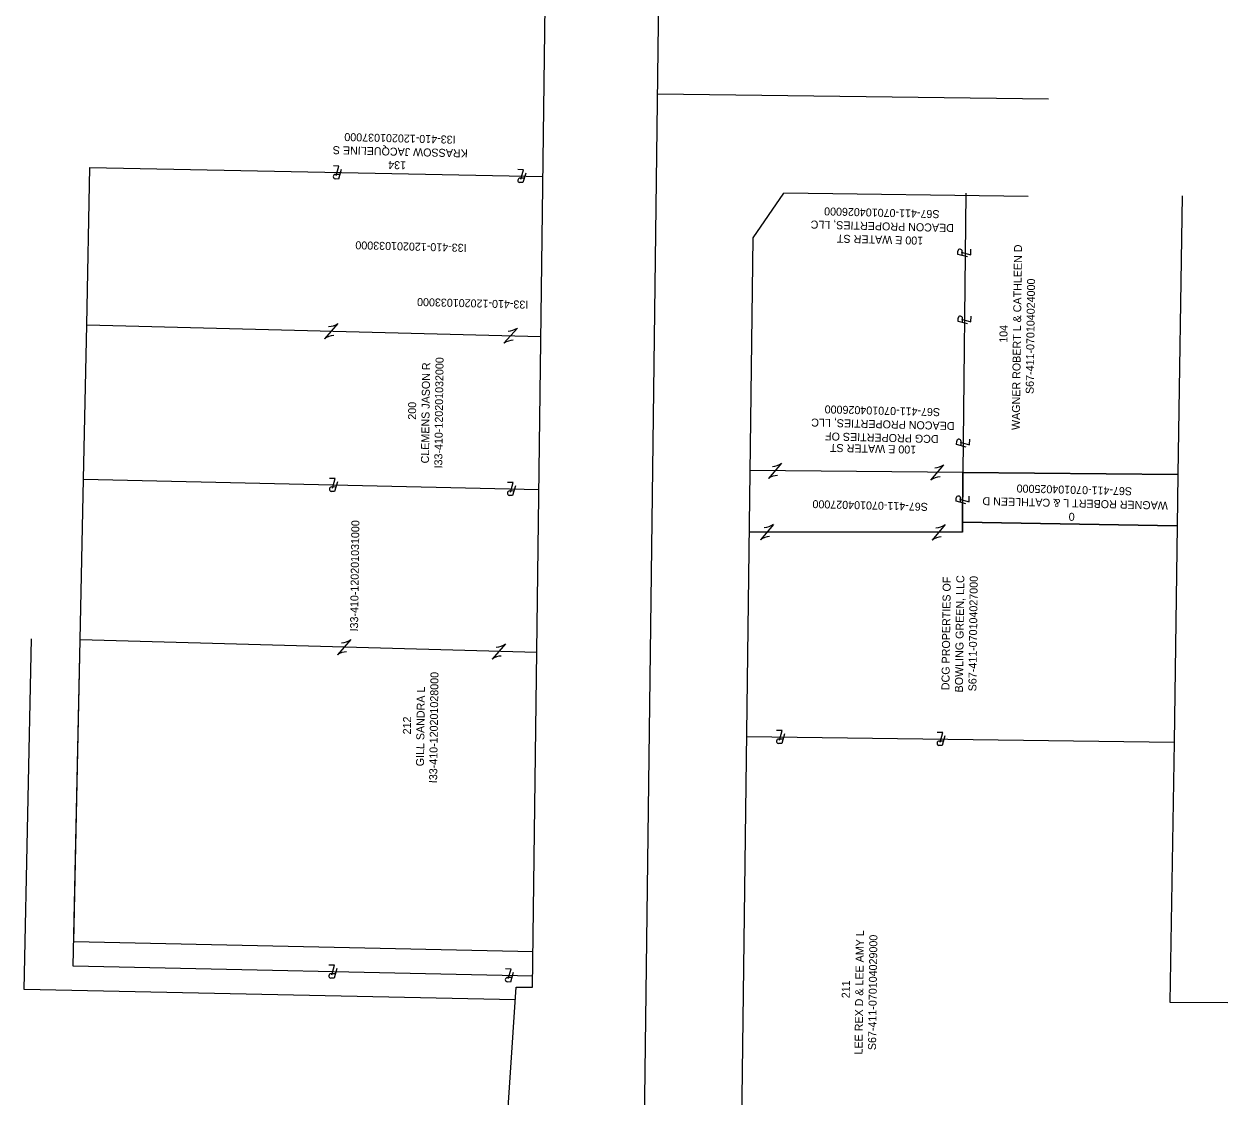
# Model space of a CAD drawing. Extents: x 1652206 to 1653153, y 604222 to 614600.
# Drawn here: x 1652350.6 to 1652721.5, y 606167.5 to 606498.1 of the extents above; entities that cross this region are included whole.
import ezdxf

# ---------------------------------------------------------------- set-up
doc = ezdxf.new("R2010")
doc.units = 0
for name, color, linetype in [('_CIVIL_CONSTRUCTION', 7, 'Continuous'), ('DT_X_Contour_Major', 7, 'Continuous'), ('GE_P_Alignment_100_Bearings', 7, 'Continuous'), ('GE_P_Alignment_100_Cardinal_Points', 7, 'Continuous'), ('GE_P_Alignment_100_Distances', 7, 'Continuous')]:
    doc.layers.add(name, color=color, linetype=linetype)

msp = doc.modelspace()

# ---------------------------------------------------------------- linework, layer by layer
at = {"layer": '_CIVIL_CONSTRUCTION'}
for p, q in [((1652516.96, 604222.43), (1652550.86, 606872.07)), ((1652666.28, 606474.95), (1652545.8, 606476.49))]:
    msp.add_line(p, q, dxfattribs=at)
at = {"layer": 'DT_X_Contour_Major'}
for p, q in [((1652350.6, 606200.67), (1652352.9, 606308.67)), ((1652365.91, 606215.35), (1652367.9, 606308.35)), ((1652507.48, 606212.3), (1652365.91, 606215.35)), ((1652502.01, 606197.42), (1652350.6, 606200.67))]:
    msp.add_line(p, q, dxfattribs=at)
at = {"layer": 'GE_P_Alignment_100_Bearings'}
for p, q in [((1652369.9, 606405.41), (1652370.9, 606453.91)), ((1652370.9, 606453.91), (1652510.47, 606451.15)), ((1652447.86, 606451.76), (1652446.56, 606451.79)), ((1652447.07, 606452.4), (1652447.07, 606452.4)), ((1652504.71, 606450.64), (1652503.41, 606450.66)), ((1652503.92, 606451.27), (1652503.92, 606451.27)), ((1652640.8, 606446.07), (1652639.83, 606359.91)), ((1652707.44, 606445.22), (1652706.07, 606359.35)), ((1652639.65, 606426.79), (1652639.66, 606428.09)), ((1652640.28, 606427.59), (1652640.28, 606427.59)), ((1652639.73, 606406.16), (1652639.75, 606407.45)), ((1652368.9, 606357.85), (1652369.9, 606405.41)), ((1652369.9, 606405.41), (1652509.84, 606401.9)), ((1652447.29, 606405.87), (1652443.17, 606401.17)), ((1652502.59, 606404.48), (1652498.47, 606399.79)), ((1652640.36, 606406.95), (1652640.36, 606406.95)), ((1652445.23, 606403.52), (1652445.23, 606403.52)), ((1652500.53, 606402.13), (1652500.53, 606402.13)), ((1652639.31, 606368.23), (1652639.32, 606369.52)), ((1652639.94, 606369.02), (1652639.94, 606369.02)), ((1652583.98, 606362.83), (1652579.94, 606358.06)), ((1652639.83, 606359.91), (1652574.32, 606360.52)), ((1652581.96, 606360.45), (1652581.96, 606360.45)), ((1652629.99, 606357.6), (1652634.04, 606362.36)), ((1652632.01, 606359.98), (1652632.01, 606359.98)), ((1652639.73, 606344.67), (1652639.83, 606359.91)), ((1652639.83, 606359.91), (1652639.73, 606344.67)), ((1652639.83, 606359.91), (1652706.07, 606359.35)), ((1652706.07, 606359.35), (1652639.83, 606359.91)), ((1652706.07, 606359.35), (1652705.85, 606343.47)), ((1652367.9, 606308.35), (1652368.9, 606357.85)), ((1652368.9, 606357.85), (1652509.24, 606354.7)), ((1652446.67, 606355.48), (1652445.37, 606355.51)), ((1652445.88, 606356.12), (1652445.88, 606356.12)), ((1652501.51, 606354.25), (1652500.22, 606354.28)), ((1652500.72, 606354.89), (1652500.72, 606354.89)), ((1652639.15, 606350.7), (1652639.16, 606352)), ((1652639.78, 606351.5), (1652639.78, 606351.5)), ((1652639.73, 606341.55), (1652639.73, 606344.67)), ((1652639.73, 606344.67), (1652705.85, 606343.47)), ((1652705.85, 606343.47), (1652639.73, 606344.67)), ((1652639.73, 606344.67), (1652639.73, 606341.55)), ((1652639.73, 606341.55), (1652574.07, 606341.59)), ((1652581.48, 606343.98), (1652577.47, 606339.19)), ((1652579.47, 606341.59), (1652579.47, 606341.59)), ((1652634.38, 606343.95), (1652630.37, 606339.15)), ((1652632.38, 606341.55), (1652632.38, 606341.55)), ((1652705.85, 606343.47), (1652704.91, 606276.91)), ((1652365.76, 606207.85), (1652367.9, 606308.35)), ((1652508.59, 606304.47), (1652367.9, 606308.35)), ((1652451.27, 606308.45), (1652447.14, 606303.76)), ((1652498.93, 606307.14), (1652494.8, 606302.45)), ((1652449.21, 606306.11), (1652449.21, 606306.11)), ((1652496.86, 606304.8), (1652496.86, 606304.8)), ((1652573.27, 606278.57), (1652704.91, 606276.91)), ((1652584.41, 606277.8), (1652583.12, 606277.82)), ((1652583.62, 606278.44), (1652583.62, 606278.44)), ((1652633.09, 606277.81), (1652633.09, 606277.81)), ((1652633.88, 606277.18), (1652632.59, 606277.2)), ((1652704.91, 606276.91), (1652703.61, 606196.79)), ((1652507.32, 606204.8), (1652365.76, 606207.85)), ((1652446.51, 606205.49), (1652445.21, 606205.52)), ((1652445.72, 606206.13), (1652445.72, 606206.13)), ((1652500.86, 606204.32), (1652499.56, 606204.35)), ((1652500.07, 606204.96), (1652500.07, 606204.96)), ((1652703.61, 606196.79), (1652721.52, 606196.61))]:
    msp.add_line(p, q, dxfattribs=at)
for points in [[(1652446.78, 606451.45), (1652447.63, 606454.39), (1652445.89, 606454.42)], [(1652448.31, 606453.34), (1652447.47, 606450.39), (1652446.44, 606450.42)], [(1652503.63, 606450.32), (1652504.48, 606453.26), (1652502.74, 606453.3)], [(1652505.16, 606452.22), (1652504.32, 606449.27), (1652503.29, 606449.29)], [(1652641.24, 606426.36), (1652638.28, 606427.16), (1652638.29, 606428.2)], [(1652639.32, 606427.86), (1652642.27, 606427.05), (1652642.28, 606428.8)], [(1652641.32, 606405.72), (1652638.36, 606406.53), (1652638.38, 606407.57)], [(1652639.41, 606407.23), (1652642.35, 606406.4), (1652642.37, 606408.15)], [(1652638.98, 606369.3), (1652641.93, 606368.47), (1652641.95, 606370.22)], [(1652640.89, 606367.79), (1652637.94, 606368.6), (1652637.95, 606369.64)], [(1652445.6, 606355.17), (1652446.45, 606358.1), (1652444.71, 606358.14)], [(1652447.13, 606357.06), (1652446.28, 606354.11), (1652445.25, 606354.14)], [(1652500.44, 606353.93), (1652501.29, 606356.87), (1652499.55, 606356.91)], [(1652501.97, 606355.83), (1652501.12, 606352.88), (1652500.09, 606352.91)], [(1652640.74, 606350.27), (1652637.78, 606351.07), (1652637.79, 606352.11)], [(1652638.82, 606351.77), (1652641.77, 606350.96), (1652641.78, 606352.71)], [(1652583.34, 606277.48), (1652584.17, 606280.43), (1652582.42, 606280.45)], [(1652584.85, 606279.39), (1652584.03, 606276.43), (1652583, 606276.45)], [(1652632.81, 606276.86), (1652633.64, 606279.8), (1652631.89, 606279.82)], [(1652634.32, 606278.77), (1652633.5, 606275.81), (1652632.47, 606275.83)], [(1652445.43, 606205.17), (1652446.29, 606208.11), (1652444.54, 606208.15)], [(1652446.96, 606207.07), (1652446.12, 606204.12), (1652445.09, 606204.15)], [(1652499.79, 606204.01), (1652500.64, 606206.95), (1652498.89, 606206.98)], [(1652501.31, 606205.9), (1652500.47, 606202.95), (1652499.44, 606202.98)]]:
    msp.add_lwpolyline(points, dxfattribs=at)
for centre, radius, start, end in [((1652446.55, 606451.1), 0.69, 89.3374, 260.1945), ((1652503.4, 606449.97), 0.69, 89.3374, 260.1945), ((1652638.97, 606428.09), 0.69, 0.0948, 170.9519), ((1652639.06, 606407.45), 0.69, 359.8263, 170.6834), ((1652444.23, 606410.25), 5.34, 272.2594, 304.902), ((1652499.54, 606408.86), 5.34, 272.2594, 304.902), ((1652446.22, 606396.79), 5.34, 92.2594, 124.902), ((1652501.53, 606395.41), 5.34, 92.2594, 124.902), ((1652638.63, 606369.52), 0.69, 359.8263, 170.6834), ((1652580.86, 606367.16), 5.34, 273.1615, 305.804), ((1652583.06, 606353.74), 5.34, 93.1615, 125.804), ((1652630.91, 606366.69), 5.34, 273.1615, 305.804), ((1652445.36, 606354.82), 0.69, 89.1851, 260.0422), ((1652633.11, 606353.27), 5.34, 93.1615, 125.804), ((1652500.21, 606353.59), 0.69, 89.1851, 260.0422), ((1652638.47, 606352), 0.69, 0.0948, 170.9519), ((1652578.32, 606348.29), 5.34, 273.6584, 306.301), ((1652631.22, 606348.25), 5.34, 273.6584, 306.301), ((1652580.63, 606334.89), 5.34, 93.6584, 126.301), ((1652633.53, 606334.85), 5.34, 93.6584, 126.301), ((1652448.23, 606312.84), 5.34, 272.117, 304.7595), ((1652495.89, 606311.52), 5.34, 272.117, 304.7595), ((1652450.18, 606299.38), 5.34, 92.117, 124.7595), ((1652497.84, 606298.07), 5.34, 92.117, 124.7595), ((1652583.11, 606277.13), 0.69, 89.749, 260.6061), ((1652632.58, 606276.51), 0.69, 89.749, 260.6061), ((1652445.2, 606204.83), 0.69, 89.2395, 260.0966), ((1652499.56, 606203.66), 0.69, 89.2395, 260.0966)]:
    msp.add_arc(centre, radius, start, end, dxfattribs=at)
at = {"layer": 'GE_P_Alignment_100_Distances'}
for p, q in [((1652575.23, 606432.27), (1652584.64, 606445.99)), ((1652659.97, 606445.03), (1652584.64, 606445.99)), ((1652570.59, 606069.16), (1652575.23, 606432.27))]:
    msp.add_line(p, q, dxfattribs=at)
for points in [[(1652507.27, 606201.32), (1652511.14, 606503.89), (1652509.15, 606503.92), (1652509.27, 606513.92), (1652511.27, 606513.89), (1652515.18, 606819.04)], [(1652491.04, 606032.77), (1652502.27, 606201.38), (1652507.27, 606201.32)]]:
    msp.add_lwpolyline(points, dxfattribs=at)

# ---------------------------------------------------------------- texts
at = {"layer": 'GE_P_Alignment_100_Cardinal_Points'}
for s, height, rotation, p in [('I33-410-120201037000', 2.4653, 178.565, (1652483.58, 606463.71)), ('KRASSOW JACQUELINE S', 2.4653, 178.565, (1652487.33, 606459.49)), ('134', 2.465, 178.565, (1652468.32, 606455.82)), ('S67-411-070104026000', 2.4653, 178.565, (1652632.69, 606440.77)), ('DEACON PROPERTIES, LLC', 2.4653, 178.565, (1652637.13, 606436.5)), ('100 E WATER ST', 2.4653, 178.565, (1652627.66, 606432.59)), ('I33-410-120201033000', 2.4653, 178.565, (1652486.98, 606430.37)), ('WAGNER ROBERT L & CATHLEEN D', 2.4653, 89.2843, (1652657.38, 606373.04)), ('S67-411-070104024000', 2.4653, 89.2843, (1652661.67, 606384.13)), ('I33-410-120201033000', 2.4653, 178.565, (1652505.99, 606412.88)), ('104', 2.465, 89.2843, (1652653.57, 606399.91)), ('CLEMENS JASON R', 2.4653, 89.2843, (1652475.34, 606362.74)), ('I33-410-120201032000', 2.4653, 89.2843, (1652479.44, 606361.19)), ('200', 2.465, 89.2843, (1652471.36, 606376.21)), ('S67-411-070104026000', 2.4653, 178.565, (1652632.86, 606379.76)), ('DEACON PROPERTIES, LLC', 2.4653, 178.565, (1652637.31, 606375.49)), ('DCG PROPERTIES OF ', 2.4653, 178.565, (1652632.41, 606371.46)), ('100 E WATER ST', 2.4653, 178.7594, (1652625.5, 606368.2)), ('S67-411-070104025000', 2.4653, 178.565, (1652692.01, 606355.38)), ('WAGNER ROBERT L & CATHLEEN D', 2.4653, 178.565, (1652703.05, 606350.95)), ('S67-411-070104027000', 2.4653, 178.565, (1652629.1, 606350.57)), ('I33-410-120201031000', 2.4653, 89.2843, (1652453.49, 606310.96)), ('0', 2.47, 178.565, (1652674.33, 606347.52)), ('DCG PROPERTIES OF', 2.4653, 89.2843, (1652635.71, 606292.86)), ('BOWLING GREEN, LLC', 2.4653, 89.2843, (1652639.86, 606292.18)), ('S67-411-070104027000', 2.4653, 89.2843, (1652644.01, 606292.51)), ('I33-410-120201028000', 2.4653, 89.2843, (1652477.86, 606264.21)), ('GILL SANDRA L', 2.4653, 89.2843, (1652473.81, 606269.41)), ('212', 2.465, 89.2843, (1652469.78, 606279.24)), ('LEE REX D & LEE AMY L', 2.4653, 89.2843, (1652608.92, 606180.6)), ('S67-411-070104029000', 2.4653, 89.2843, (1652613.09, 606181.95)), ('211', 2.465, 89.2843, (1652604.99, 606197.96))]:
    msp.add_text(s, height=height, rotation=rotation, dxfattribs=at).set_placement(p)

doc.saveas('drawing.dxf')
